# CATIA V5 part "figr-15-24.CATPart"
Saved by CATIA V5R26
Part number: Part1
Bounding box of the stored display mesh (mm): x -50 to 50, y -25 to 25, z -24 to 1
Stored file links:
  D:\_Deepak\CATIA\CATIA V5-6R2016_Deepak\Resources\Part files\Partfiles\c15_catia_v5_6r2016_prt\figr-15-24.CATPart
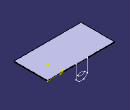
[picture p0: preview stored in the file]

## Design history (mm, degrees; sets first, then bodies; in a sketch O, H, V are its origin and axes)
SheetMetalParameters1: Thickness 1, BendRadius 2, KFactor 0.400515 {= log(min(100,max(20*SheetMetalParameters1.BendRadius,SheetMetalParameters1.Thickness)/SheetMetalParameters1.Thickness))/log(100)/2}, ReliefRadialLength 1, ReliefAxialLength 2, MinimumBendRadius 0
Body1 (main body)
  Sketch1 on xy-plane, origin (0, 0, 0), H (1, 0, 0), V (0, 1, 0)
    line L1 (-50, 25) -> (50, 25)
    line L2 (50, 25) -> (50, -25)
    line L3 (50, -25) -> (-50, -25)
    line L4 (-50, -25) -> (-50, 25)
    length L1 = 100
    distance V L2 = 50
    length L2 = 50
    distance H L3 = 25
    horizontal: L1 H, L3 H
    vertical: L2 V, L4 V
  Wall1: Thickness 1, Profile Sketch1
  Sketch2 on face of Wall1, origin (50, 25, 0), H (-1, 0, 0), V (0, 0, 1)
    line L1 (42.3549, 1) -> (42.3549, -19)
    point P2 (42.3549, -19)
    line L2 (42.3549, -19) -> (47.3549, -24)
    point P3 (47.3549, -24)
    line L3 (47.3549, -24) -> (54.3549, -24)
    point P4 (54.3549, -24)
    line L4 (54.3549, -24) -> (59.3549, -19)
    point P5 (59.3549, -19)
    line L5 (59.3549, -19) -> (59.3549, 1)
    line L6 (59.3549, 1) -> (42.3549, 1)
    reference projected line E1 (100, 1) -> (0, 1) from edge [face of Wall1 | face of Wall1]
    ellipse A1 centre (50.1164, -15.2153) semi-axes 5.0583, 2.1402 rotation 0
    length L5 = 20
    length L1 = 20
    length L3 = 7
    distance P4 L5 = 5
    distance P2 P3 H = 5
    distance L3 P5 = 5
    vertical: L1 V, L5 V
    horizontal: L3 H, L6 H
    coincidence: L6 E1
    parallelism: A1 L3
